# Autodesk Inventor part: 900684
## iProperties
Created: 2007-10
Part Number: 900684
Document SubType Name: Modeling
Designer: TH
Density: 1.13 g/cm^3
Mass: 11.2298 g
Surface Area: 57.4477 cm^2
Volume: 9.93789 cm^3
Material: Nylon Composite (Nylon, molybdenum disulphide)
Description: MOTOR SIDE COVER AND MOUNT
Component Category: Electrical
Author: TH
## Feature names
1. Revolution1
2. Extrusion1
3. Extrusion2
4. Extrusion3
5. Extrusion4
6. Fillet2
7. Fillet3
8. Fillet4
9. Extrusion5
10. Fillet5
